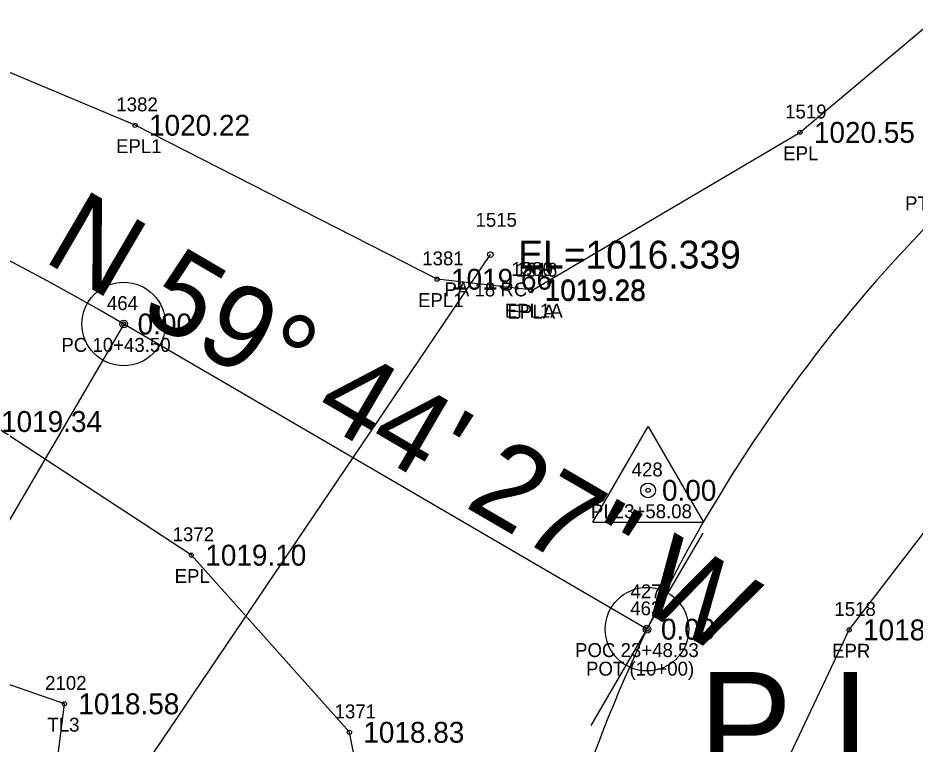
# Model space of a CAD drawing. Extents: x 1578957 to 1581675, y 1115963 to 1120391.
# Drawn here: x 1580096.1 to 1580160.5, y 1117657.3 to 1117709.5 of the extents above; entities that cross this region are included whole.
import ezdxf

# ---------------------------------------------------------------- set-up
doc = ezdxf.new("R2010")
doc.units = 0
for name, color, linetype in [('RD_EX_DR_Pipe', 7, 'Continuous'), ('RD_EX_DR_Pipe_txCode', 7, 'Continuous'), ('RD_EX_Road', 7, 'Continuous'), ('RD_EX_Road_txCode', 7, 'Continuous'), ('RD_EX_TX_Road_ELEV', 7, 'Continuous'), ('RD_EX_TX_VEG_ELEV', 7, 'Continuous'), ('RD_EX_VEG', 7, 'Continuous'), ('RD_EX_VEG_txCode', 7, 'Continuous'), ('RD_HC_Cl', 7, 'Continuous'), ('RD_HC_Data', 7, 'Continuous'), ('RD_HC_Data_Tic', 7, 'Continuous'), ('RD_HC_Survey_ELEV', 7, 'Continuous'), ('RD_HC_txCode', 7, 'Continuous'), ('RD_SMD_Locator', 7, 'Continuous'), ('RD_TX_Pipe_ElevEX', 7, 'Continuous')]:
    doc.layers.add(name, color=color, linetype=linetype)

msp = doc.modelspace()

# ---------------------------------------------------------------- linework, layer by layer
at = {"layer": 'RD_EX_DR_Pipe'}
msp.add_line((1580130.018, 1117692.482), (1580101.554, 1117650.394), dxfattribs=at)
at = {"layer": 'RD_EX_Road'}
for points in [[(1580132.944, 1117689.892), (1580152.251, 1117701.26), (1580167.399, 1117714.022), (1580202.848, 1117747.921), (1580240.97, 1117781.029), (1580278.217, 1117814.009), (1580314.49, 1117848.76), (1580346.173, 1117886.723), (1580374.273, 1117928.325), (1580397.158, 1117972.415), (1580413.485, 1118019.658), (1580424.922, 1118067.62), (1580431.487, 1118116.976), (1580436.813, 1118166.419), (1580442.562, 1118216.328), (1580451.482, 1118265.257), (1580462.53, 1118314.081), (1580473.875, 1118362.545), (1580483.476, 1118411.51)], [(1580144.445, 1117641.553), (1580155.785, 1117665.527), (1580181.996, 1117699.63), (1580215.512, 1117732.12), (1580254.236, 1117765.944), (1580291.41, 1117798.887), (1580327.792, 1117833.809), (1580361.61, 1117873.472), (1580391.536, 1117917.746), (1580415.571, 1117964.645), (1580432.494, 1118014.023), (1580444.751, 1118063.232), (1580451.681, 1118114.823), (1580456.808, 1118164.405), (1580462.655, 1118213.644), (1580471.15, 1118260.763), (1580481.728, 1118308.533), (1580493.79, 1118358.466), (1580503.62, 1118407.198)], [(1580132.914, 1117689.949), (1580126.197, 1117690.713), (1580104.514, 1117701.773), (1580054.231, 1117722.915), (1579999.655, 1117728.645), (1579947.034, 1117725.641), (1579902.617, 1117727.901), (1579859.282, 1117741.23), (1579828.335, 1117764.868), (1579804.422, 1117802.726), (1579793.197, 1117845.912), (1579792.758, 1117891.982), (1579799.628, 1117938.215), (1579807.414, 1117987.508), (1579809.684, 1118039.768), (1579804.464, 1118093.359), (1579794.793, 1118143.944)], [(1580121.995, 1117647.598), (1580119.902, 1117658.172), (1580108.554, 1117670.894), (1580093.888, 1117680.496), (1580047.657, 1117700.115), (1579998.943, 1117706.513), (1579949.017, 1117704.446), (1579899.181, 1117706.754), (1579851.312, 1117721.596), (1579810.789, 1117752.923), (1579804.028, 1117759.706), (1579792.304, 1117778.187), (1579787.439, 1117787.947), (1579779.119, 1117811.184), (1579772.603, 1117842.297), (1579771.808, 1117848.588), (1579770.145, 1117878.236), (1579771.725, 1117892.019), (1579778.922, 1117940.842), (1579785.853, 1117982.888), (1579786.73, 1117990.339), (1579789.156, 1118040.245), (1579783.452, 1118089.738), (1579774.288, 1118139.394)]]:
    msp.add_lwpolyline(points, dxfattribs=at)
at = {"layer": 'RD_EX_VEG'}
msp.add_lwpolyline([(1579862.335, 1117508.136), (1579987.98, 1117577.137), (1580030.014, 1117601.023), (1580092.8, 1117606.943), (1580099.438, 1117660.216), (1579997.235, 1117695.776), (1579947.95, 1117691.884), (1579838.071, 1117719.77), (1579796.802, 1117753.004), (1579780.494, 1117738.535), (1579705.634, 1117750.62)], dxfattribs=at)
at = {"layer": 'RD_HC_Cl'}
msp.add_line((1580141.268, 1117665.576), (1580103.693, 1117687.498), dxfattribs=at)
for centre, radius, start, end in [((1579994.833, 1117500.9), 216.03, 59.74089, 93.23235), ((1580240.27, 1117618.342), 109.692, 133.6822, 166.23684)]:
    msp.add_arc(centre, radius, start, end, dxfattribs=at)
at = {"layer": 'RD_HC_Data'}
for p, q in [((1580103.693, 1117687.498), (1580044.891, 1117586.706)), ((1580137.377, 1117673.255), (1580141.349, 1117680.135)), ((1580141.349, 1117680.135), (1580145.317, 1117673.255)), ((1580137.377, 1117673.255), (1580145.317, 1117673.255))]:
    msp.add_line(p, q, dxfattribs=at)
for centre, radius in [((1580103.693, 1117687.498), 3), ((1580103.693, 1117687.498), 0.282), ((1580141.347, 1117675.548), 0.529), ((1580141.268, 1117665.576), 3), ((1580141.268, 1117665.576), 3), ((1580141.268, 1117665.576), 0.282), ((1580141.268, 1117665.576), 0.282)]:
    msp.add_circle(centre, radius, dxfattribs=at)
at = {"layer": 'RD_HC_Data_Tic'}
for q in [(1580145.3, 1117672.486), (1580137.237, 1117658.666)]:
    msp.add_line((1580141.268, 1117665.576), q, dxfattribs=at)
at = {"layer": 'RD_SMD_Locator'}
for centre, radius in [((1580104.514, 1117701.773), 0.15), ((1580152.251, 1117701.26), 0.15), ((1580130.018, 1117692.482), 0.2), ((1580126.197, 1117690.713), 0.15), ((1580132.914, 1117689.949), 0.15), ((1580132.944, 1117689.892), 0.15), ((1580103.693, 1117687.498), 0.15), ((1580141.347, 1117675.548), 0.15), ((1580108.554, 1117670.894), 0.15), ((1580141.268, 1117665.576), 0.15), ((1580141.268, 1117665.576), 0.15), ((1580155.785, 1117665.527), 0.15), ((1580099.438, 1117660.216), 0.15), ((1580119.902, 1117658.172), 0.15)]:
    msp.add_circle(centre, radius, dxfattribs=at)

# ---------------------------------------------------------------- texts
at = {"layer": 'RD_EX_DR_Pipe_txCode'}
for s, p in [('1515', (1580128.955, 1117694.482)), ('PA 18 RC', (1580126.727, 1117689.482))]:
    msp.add_text(s, height=1, dxfattribs=at).set_placement(p)
at = {"layer": 'RD_EX_Road_txCode'}
for s, p in [('1382', (1580103.167, 1117702.773)), ('1519', (1580151.188, 1117702.26)), ('EPL1', (1580103.143, 1117699.773)), ('EPL', (1580151.046, 1117699.26)), ('1381', (1580125.134, 1117691.713)), ('1380', (1580131.528, 1117690.949)), ('1516', (1580131.857, 1117690.892)), ('EPL1', (1580124.827, 1117688.713)), ('EPL1A', (1580131.056, 1117687.949)), ('EPLA', (1580131.251, 1117687.892)), ('1372', (1580107.208, 1117671.894)), ('EPL', (1580107.35, 1117668.894)), ('1518', (1580154.722, 1117666.527)), ('EPR', (1580154.557, 1117663.527)), ('1371', (1580118.839, 1117659.172))]:
    msp.add_text(s, height=1, dxfattribs=at).set_placement(p)
at = {"layer": 'RD_EX_TX_Road_ELEV'}
for s, p in [('1020.22', (1580105.514, 1117701.023)), ('1020.55', (1580153.251, 1117700.51)), ('1019.66', (1580127.197, 1117689.963)), ('1019.28', (1580133.914, 1117689.199)), ('1019.28', (1580133.944, 1117689.142)), ('1019.34', (1580094.888, 1117679.746)), ('1019.10', (1580109.554, 1117670.144)), ('1018.74', (1580156.785, 1117664.777)), ('1018.83', (1580120.902, 1117657.422))]:
    msp.add_text(s, height=1.5, dxfattribs=at).set_placement(p)
at = {"layer": 'RD_EX_TX_VEG_ELEV'}
msp.add_text('1018.58', height=1.5, dxfattribs=at).set_placement((1580100.438, 1117659.466))
at = {"layer": 'RD_EX_VEG_txCode'}
for s, p in [('2102', (1580098.052, 1117661.216)), ('TL3', (1580098.217, 1117658.216))]:
    msp.add_text(s, height=1, dxfattribs=at).set_placement(p)
at = {"layer": 'RD_HC_Data'}
for s, rotation, p in [('N 59%%d 44\' 27" W', 329.74089, (1580097.786, 1117692.101)), ('N 64%%d 40\' 56" E', 25.31783, (1580153.991, 1117636.365))]:
    msp.add_text(s, height=6, rotation=rotation, dxfattribs=at).set_placement(p)
msp.add_text('P.I. = 23+58.08', height=7.5, dxfattribs=at).set_placement((1580145, 1117655))
at = {"layer": 'RD_HC_Survey_ELEV'}
for p in [(1580104.693, 1117686.748), (1580142.347, 1117674.798), (1580142.268, 1117664.826), (1580142.268, 1117664.826)]:
    msp.add_text('0.00', height=1.5, dxfattribs=at).set_placement(p)
at = {"layer": 'RD_HC_txCode'}
for s, p in [('PT 23+88.37', (1580159.801, 1117695.669)), ('464', (1580102.488, 1117688.498)), ('PC 10+43.50', (1580099.22, 1117685.498)), ('428', (1580140.166, 1117676.548)), ('PI 23+58.08', (1580137.245, 1117673.548)), ('427', (1580140.082, 1117667.795)), ('463', (1580140.064, 1117666.576)), ('POC 23+48.53', (1580136.103, 1117663.576)), ('POT (10+00)', (1580136.89, 1117662.241))]:
    msp.add_text(s, height=1, dxfattribs=at).set_placement(p)
at = {"layer": 'RD_TX_Pipe_ElevEX'}
msp.add_text('EL=1016.339', height=2, dxfattribs=at).set_placement((1580132.018, 1117691.482))

doc.saveas('drawing.dxf')
